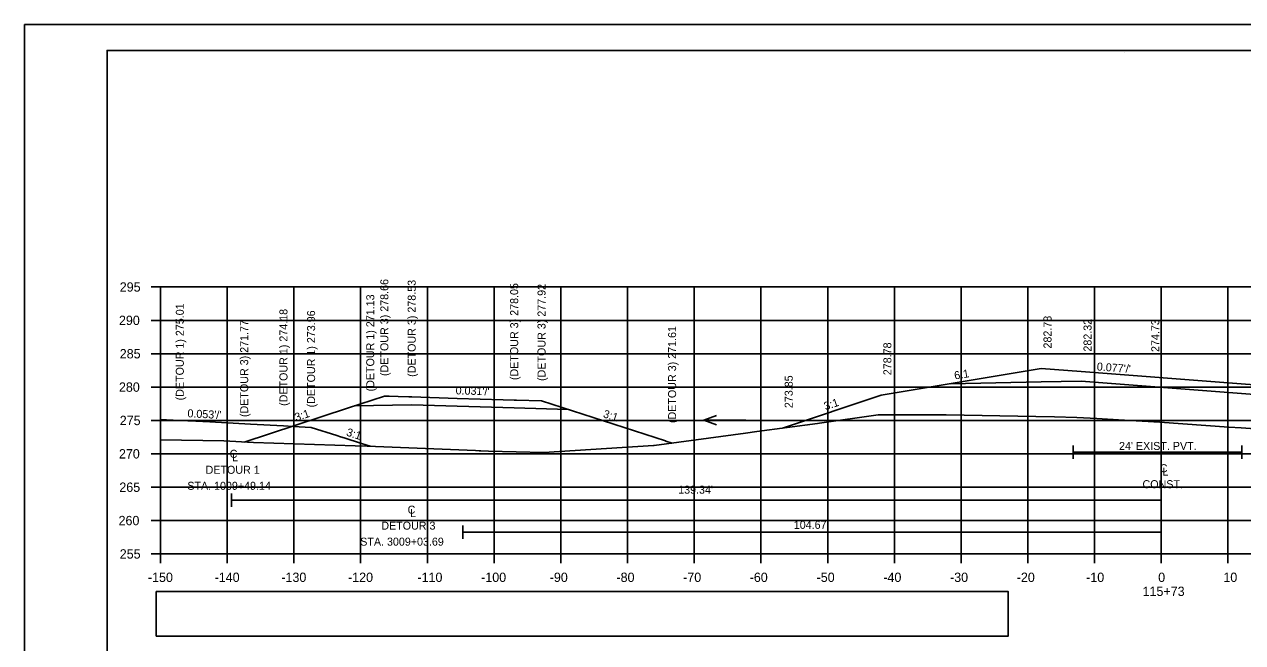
# Model space of a CAD drawing. Extents: x 285 to 4233, y -659 to 3710.
# Drawn here: x 2389.1 to 2571.7, y 523.5 to 616.2 of the extents above; entities that cross this region are included whole.
import ezdxf

# ---------------------------------------------------------------- set-up
doc = ezdxf.new("R2010")
doc.units = 0
for name, color, linetype in [('R_Alt Surface', 7, 'Continuous'), ('R_Axis', 7, 'Continuous'), ('R_Axis Annot', 7, 'Continuous'), ('R_Border', 7, 'Continuous'), ('R_Detour', 7, 'Continuous'), ('R_Exist Surface', 7, 'Continuous'), ('R_Fin Surface', 7, 'Continuous'), ('R_Grid', 7, 'Continuous'), ('R_No Plot', 7, 'Continuous'), ('R_Water', 7, 'Continuous'), ('R_Water Annot', 7, 'Continuous'), ('R_Xsect Elev', 7, 'Continuous'), ('R_Xsect Slope', 7, 'Continuous')]:
    doc.layers.add(name, color=color, linetype=linetype)

msp = doc.modelspace()

# ---------------------------------------------------------------- linework, layer by layer
at = {"layer": 'R_Alt Surface'}
for points in [[(2527.89, 562.34), (2541.5, 562.61), (2547.5, 562.73), (2547.5, 562.73), (2573.5, 560.74), (2581.5, 560.13), (2597.23, 558.92)], [(2546.32, 553.07), (2546.32, 551.07)], [(2546.32, 552.07), (2571.56, 552.07)], [(2571.56, 553.07), (2571.56, 551.07)], [(2420.16, 545.88), (2420.16, 543.88)], [(2420.16, 544.88), (2559.5, 544.88)], [(2559.5, 545.88), (2559.5, 542.58)], [(2559.5, 542.58), (2559.5, 539.09)], [(2454.83, 541.09), (2454.83, 539.09)], [(2454.83, 540.09), (2559.5, 540.09)]]:
    msp.add_lwpolyline(points, dxfattribs=at)
at = {"layer": 'R_Axis'}
for p, q in [((2408.1, 576.83), (2409.5, 576.83)), ((2409.5, 536.83), (2409.5, 576.83)), ((2408.1, 571.83), (2409.5, 571.83)), ((2408.1, 566.83), (2409.5, 566.83)), ((2408.1, 561.83), (2409.5, 561.83)), ((2408.1, 556.83), (2409.5, 556.83)), ((2408.1, 551.83), (2409.5, 551.83)), ((2408.1, 546.83), (2409.5, 546.83)), ((2408.1, 541.83), (2409.5, 541.83)), ((2408.1, 536.83), (2409.5, 536.83)), ((2409.5, 536.83), (2709.5, 536.83)), ((2409.5, 535.43), (2409.5, 536.83)), ((2419.5, 535.43), (2419.5, 536.83)), ((2429.5, 535.43), (2429.5, 536.83)), ((2439.5, 535.43), (2439.5, 536.83)), ((2449.5, 535.43), (2449.5, 536.83)), ((2459.5, 535.43), (2459.5, 536.83)), ((2469.5, 535.43), (2469.5, 536.83)), ((2479.5, 535.43), (2479.5, 536.83)), ((2489.5, 535.43), (2489.5, 536.83)), ((2499.5, 535.43), (2499.5, 536.83)), ((2509.5, 535.43), (2509.5, 536.83)), ((2519.5, 535.43), (2519.5, 536.83)), ((2529.5, 535.43), (2529.5, 536.83)), ((2539.5, 535.43), (2539.5, 536.83)), ((2549.5, 535.43), (2549.5, 536.83)), ((2559.5, 535.43), (2559.5, 536.83)), ((2569.5, 535.43), (2569.5, 536.83))]:
    msp.add_line(p, q, dxfattribs=at)
at = {"layer": 'R_Axis Annot'}
msp.add_lwpolyline([(2408.87, 524.53), (2536.56, 524.53), (2536.56, 531.18), (2408.87, 531.18)], close=True, dxfattribs=at)
at = {"layer": 'R_Border'}
for p, q in [((2401.5, 612.29), (2717.68, 612.29)), ((2401.5, 406.83), (2401.5, 612.29)), ((2554.02, 612.03), (2554.02, 612.03)), ((2554.02, 612.03), (2554.02, 612.03))]:
    msp.add_line(p, q, dxfattribs=at)
at = {"layer": 'R_Detour'}
for points in [[(2422.04, 553.6), (2437.55, 558.69), (2443.05, 560.49), (2443.78, 560.46), (2445.12, 560.42), (2446.73, 560.37), (2447.15, 560.36), (2453.95, 560.14), (2460.86, 559.93), (2462.51, 559.88), (2462.87, 559.87), (2466.61, 559.75), (2483.62, 554.26), (2485.17, 553.76), (2485.26, 553.73), (2486.18, 553.44)], [(2438.53, 559), (2447.15, 559.19), (2462.51, 558.71), (2470.6, 558.46)], [(2409.5, 556.99), (2410.42, 556.94), (2412.39, 556.84), (2414.79, 556.71), (2416.87, 556.6), (2422.99, 556.27), (2427.93, 556.01), (2429.36, 555.93), (2432.07, 555.79), (2435.92, 554.56), (2436.47, 554.38), (2437.02, 554.21), (2439.61, 553.38), (2440.94, 552.96)]]:
    msp.add_lwpolyline(points, dxfattribs=at)
at = {"layer": 'R_Exist Surface'}
msp.add_lwpolyline([(2409.5, 553.95), (2419.01, 553.77), (2423.45, 553.52), (2438.67, 553.04), (2440.48, 552.99), (2456.69, 552.31), (2457.24, 552.29), (2457.53, 552.28), (2458.67, 552.25), (2466.98, 552.02), (2483.4, 553.06), (2483.42, 553.06), (2483.51, 553.07), (2497.16, 554.95), (2498.89, 555.17), (2507.99, 556.38), (2508.26, 556.42), (2517.07, 557.67), (2520.25, 557.67), (2527.27, 557.68), (2540.69, 557.42), (2543.5, 557.36), (2546.87, 557.27), (2549.85, 557.1), (2553.09, 556.92), (2559.29, 556.57), (2569.61, 555.83), (2571.49, 555.71), (2579.8, 555.12)], dxfattribs=at)
at = {"layer": 'R_Fin Surface'}
msp.add_lwpolyline([(2502.71, 555.68), (2517.5, 560.61), (2541.5, 564.61), (2547.5, 564.15), (2571.5, 562.31), (2573.5, 562.16), (2581.5, 561.54), (2601.5, 558.21), (2622.35, 551.26), (2634.33, 555.25)], dxfattribs=at)
at = {"layer": 'R_Grid'}
for p, q in [((2409.5, 576.83), (2709.5, 576.83)), ((2409.5, 536.83), (2409.5, 576.83)), ((2419.5, 536.83), (2419.5, 576.83)), ((2429.5, 536.83), (2429.5, 576.83)), ((2439.5, 536.83), (2439.5, 576.83)), ((2449.5, 536.83), (2449.5, 576.83)), ((2459.5, 536.83), (2459.5, 576.83)), ((2469.5, 536.83), (2469.5, 576.83)), ((2479.5, 536.83), (2479.5, 576.83)), ((2489.5, 536.83), (2489.5, 576.83)), ((2499.5, 536.83), (2499.5, 576.83)), ((2509.5, 536.83), (2509.5, 576.83)), ((2519.5, 536.83), (2519.5, 576.83)), ((2529.5, 536.83), (2529.5, 576.83)), ((2539.5, 536.83), (2539.5, 576.83)), ((2549.5, 536.83), (2549.5, 576.83)), ((2559.5, 536.83), (2559.5, 576.83)), ((2569.5, 536.83), (2569.5, 576.83)), ((2409.5, 571.83), (2709.5, 571.83)), ((2409.5, 566.83), (2709.5, 566.83)), ((2409.5, 561.83), (2709.5, 561.83)), ((2409.5, 556.83), (2709.5, 556.83)), ((2409.5, 551.83), (2709.5, 551.83)), ((2409.5, 546.83), (2709.5, 546.83)), ((2409.5, 541.83), (2709.5, 541.83)), ((2409.5, 536.83), (2709.5, 536.83))]:
    msp.add_line(p, q, dxfattribs=at)
at = {"layer": 'R_No Plot'}
msp.add_line((2389.1, 616.18), (2722.43, 616.18), dxfattribs=at)
for points in [[(2389.09, 616.18), (2722.43, 616.18), (2722.43, 402.85), (2389.09, 402.85)], [(2635.42, 612.29), (2655.04, 612.29), (2655.04, 602.41), (2671.15, 602.41), (2694.35, 602.41), (2694.47, 574.25), (2717.68, 574.25), (2717.68, 406.83), (2401.5, 406.83), (2401.5, 612.29)]]:
    msp.add_lwpolyline(points, close=True, dxfattribs=at)
at = {"layer": 'R_Water Annot'}
for p, q in [((2490.93, 556.87), (2492.85, 557.57)), ((2497.21, 556.87), (2490.93, 556.87)), ((2490.93, 556.87), (2492.85, 556.17))]:
    msp.add_line(p, q, dxfattribs=at)
at = {"layer": 'R_Xsect Elev'}
msp.add_line((2559.5, 556.56), (2559.5, 572.92), dxfattribs=at)

# ---------------------------------------------------------------- texts
at = {"layer": 'R_Alt Surface'}
for s, height, p in [('C', 1.2, (2419.87, 551.23)), ('L', 1.2, (2420.25, 550.7)), ('DETOUR 1', 1.199, (2416.26, 548.84)), ('C', 1.2, (2559.28, 549.07)), ('L', 1.2, (2559.66, 548.55)), ('CONST.', 1.199, (2556.69, 546.68)), ('STA. 1009+49.14', 1.1985, (2413.52, 546.44)), ('C', 1.2, (2446.54, 542.86)), ('L', 1.2, (2446.93, 542.34)), ('DETOUR 3', 1.199, (2442.6, 540.47)), ('STA. 3009+03.69', 1.1985, (2439.44, 538.07))]:
    msp.add_text(s, height=height, dxfattribs=at).set_placement(p)
at = {"layer": 'R_Axis Annot'}
for s, p in [('295', (2403.39, 576.13)), ('290', (2403.27, 571.13)), ('285', (2403.39, 566.13)), ('280', (2403.27, 561.13)), ('275', (2403.39, 556.13)), ('270', (2403.27, 551.13)), ('265', (2403.33, 546.13)), ('260', (2403.21, 541.13)), ('255', (2403.39, 536.13)), ('-150', (2407.61, 532.63)), ('-140', (2417.61, 532.63)), ('-130', (2427.61, 532.63)), ('-120', (2437.61, 532.63)), ('-110', (2448.01, 532.63)), ('-100', (2457.56, 532.63)), ('-90', (2467.84, 532.63)), ('-80', (2477.84, 532.63)), ('-70', (2487.84, 532.63)), ('-60', (2497.81, 532.63)), ('-50', (2507.84, 532.63)), ('-40', (2517.84, 532.63)), ('-30', (2527.84, 532.63)), ('-20', (2537.84, 532.63)), ('-10', (2548.24, 532.63)), ('0', (2559.04, 532.63)), ('10', (2568.81, 532.63)), ('115+73', (2556.7, 530.53))]:
    msp.add_text(s, height=1.4, dxfattribs=at).set_placement(p)
at = {"layer": 'R_Water'}
for s, p in [("24' EXIST. PVT.", (2553.17, 552.41)), ("139.34'", (2487.09, 545.86)), ("104.67'", (2504.42, 540.59))]:
    msp.add_text(s, height=1.2, dxfattribs=at).set_placement(p)
at = {"layer": 'R_Xsect Elev'}
for s, p in [('(DETOUR 3) 278.66', (2443.65, 563.49)), ('(DETOUR 3) 278.53', (2447.75, 563.36)), ('(DETOUR 3) 278.05', (2463.11, 562.88)), ('(DETOUR 3) 277.92', (2467.21, 562.75)), ('(DETOUR 1) 271.13', (2441.54, 561.18)), ('(DETOUR 1) 275.01', (2412.99, 559.84)), ('(DETOUR 1) 274.18', (2428.53, 559.01)), ('(DETOUR 3) 271.77', (2422.64, 557.34)), ('(DETOUR 1) 273.96', (2432.67, 558.79)), ('282.78', (2543.05, 567.61)), ('282.32', (2549.05, 567.15)), ('274.73', (2559.2, 567.09)), ('(DETOUR 3) 271.61', (2486.78, 556.44)), ('278.78', (2519.05, 563.61)), ('273.85', (2504.26, 558.68))]:
    msp.add_text(s, height=1.2, rotation=90, dxfattribs=at).set_placement(p)
at = {"layer": 'R_Xsect Slope'}
for s, rotation, p in [('6:1', 9.4623, (2528.57, 562.96)), ("0.077'/'", 355.6187, (2549.81, 564.33)), ("0.031'/'", 358.2183, (2453.72, 560.75)), ('3:1', 18.4349, (2509.16, 558.35)), ("0.053'/'", 356.9387, (2413.51, 557.32)), ('3:1', 18.1448, (2429.84, 556.7)), ('3:1', 342.113, (2475.75, 557.33)), ('3:1', 342.3057, (2437.26, 554.58))]:
    msp.add_text(s, height=1.2, rotation=rotation, dxfattribs=at).set_placement(p)

doc.saveas('drawing.dxf')
